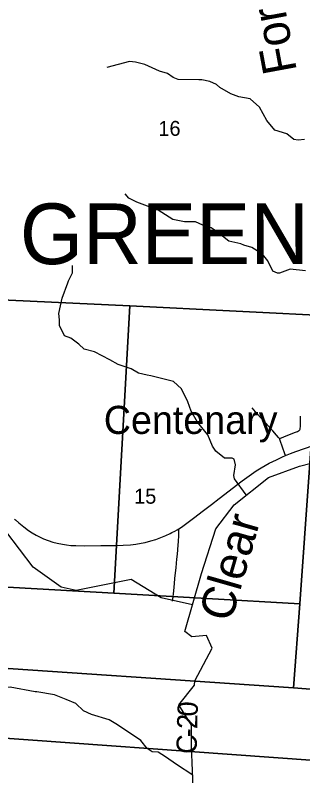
# Model space of a CAD drawing. Extents: x 0 to 34, y 0 to 22.
# Drawn here: x 24.586 to 25.392, y 17.797 to 19.934 of the extents above; entities that cross this region are included whole.
import ezdxf

# ---------------------------------------------------------------- set-up
doc = ezdxf.new("R2010")
doc.units = 0
for name, color, linetype in [('GM_X_County_Road', 7, 'Continuous'), ('GM_X_County_Road_Text', 7, 'Continuous'), ('GM_X_Minor_River', 7, 'Continuous'), ('GM_X_Minor_River_Text', 7, 'Continuous'), ('GM_X_Section', 7, 'Continuous'), ('GM_X_Section_Text', 7, 'Continuous'), ('GM_X_State_Route', 7, 'Continuous'), ('GM_X_Township_Road', 7, 'Continuous'), ('GM_X_Township_Text', 7, 'Continuous'), ('GM_X_Unincorporated_Text', 7, 'Continuous')]:
    doc.layers.add(name, color=color, linetype=linetype)

msp = doc.modelspace()

# ---------------------------------------------------------------- linework, layer by layer
at = {"layer": 'GM_X_County_Road'}
msp.add_lwpolyline([(25.0271, 18.2869), (25.0277, 18.2919), (25.0303, 18.3166), (25.0323, 18.337), (25.0337, 18.3509), (25.0354, 18.3666), (25.0368, 18.3808), (25.0382, 18.3939), (25.0393, 18.4054), (25.0405, 18.419), (25.0417, 18.4316), (25.0428, 18.4456), (25.0434, 18.4539), (25.0442, 18.4732), (25.0443, 18.4852), (25.0443, 18.4908)], dxfattribs=at)
at = {"layer": 'GM_X_Minor_River'}
for points in [[(25.3973, 19.5841), (25.3794, 19.583), (25.3669, 19.5845), (25.3472, 19.6004), (25.3142, 19.611), (25.2911, 19.6376), (25.2711, 19.6756), (25.2445, 19.6988), (25.2131, 19.7041), (25.1907, 19.7124), (25.1596, 19.7306), (25.1505, 19.739), (25.1312, 19.7477), (25.1092, 19.7518), (25.1009, 19.7518), (25.0425, 19.7529), (25.0289, 19.7586), (25.0129, 19.7704), (24.9906, 19.7768), (24.9489, 19.7954), (24.9231, 19.8022), (24.906, 19.8037), (24.8427, 19.7865)], [(25.4002, 19.2158), (25.3566, 19.2203), (25.327, 19.2089), (25.3209, 19.2085), (25.3084, 19.2145), (25.294, 19.2434), (25.2796, 19.262), (25.2497, 19.2806), (25.2273, 19.2874), (25.2182, 19.2909), (25.1849, 19.2992), (25.1493, 19.3269), (25.1348, 19.336), (25.122, 19.3394), (25.0909, 19.3534), (25.0602, 19.3534), (25.028, 19.3598), (24.9866, 19.386), (24.9264, 19.4084), (24.9044, 19.4194), (24.8942, 19.4323)], [(25.2332, 18.5859), (25.2006, 18.6309), (25.199, 18.6404), (25.2036, 18.67), (25.1994, 18.6864), (25.1945, 18.689), (25.1722, 18.689), (25.1483, 18.7091), (25.1392, 18.7232), (25.1263, 18.7551), (25.0971, 18.7901), (25.0789, 18.8216), (25.0702, 18.8478), (25.0517, 18.8843), (25.0293, 18.9044), (24.966, 18.9203), (24.9558, 18.9226), (24.9311, 18.9283), (24.9107, 18.94), (24.8743, 18.9525), (24.8512, 18.965), (24.808, 18.9882), (24.7792, 18.995), (24.7644, 19.0098), (24.742, 19.0265), (24.7242, 19.0329), (24.7102, 19.0618), (24.7102, 19.0782), (24.7079, 19.0953), (24.7174, 19.1386), (24.7334, 19.182), (24.7353, 19.1877), (24.7459, 19.2101), (24.7459, 19.2307)], [(25.0861, 17.7413), (25.0798, 17.8798), (25.0798, 17.9386), (25.0441, 17.9963), (25.0881, 18.0514), (25.0891, 18.0639), (25.1376, 18.1555), (25.1224, 18.191), (25.081, 18.1868), (25.0611, 18.2022), (25.1079, 18.3651), (25.1484, 18.4907), (25.1999, 18.558), (25.2957, 18.6351), (25.3826, 18.667), (25.4443, 18.6827)], [(25.0825, 18.2766), (24.9949, 18.2969), (24.9111, 18.3481), (24.7563, 18.3171), (24.7148, 18.3263), (24.6358, 18.3825), (24.5593, 18.4839)], [(25.0835, 17.7983), (25.0376, 17.8285), (25.0069, 17.8501), (24.9869, 17.8627), (24.9698, 17.8645), (24.9562, 17.8737), (24.9376, 17.8961), (24.8728, 17.9401), (24.8489, 17.9538), (24.7996, 17.9689), (24.7769, 17.9795), (24.7561, 18), (24.7284, 18.0107), (24.6954, 18.0239), (24.6461, 18.0322), (24.6416, 18.033), (24.5711, 18.0455), (24.54, 18.0409), (24.5021, 18.0446), (24.4869, 18.0457), (24.4562, 18.0396), (24.424, 18.0415), (24.3853, 18.0434), (24.3577, 18.0384)]]:
    msp.add_lwpolyline(points, dxfattribs=at)
at = {"layer": 'GM_X_Section'}
for points in [[(24.5388, 20.1708), (25.5703, 20.1097), (25.5433, 19.6923), (25.5164, 19.2759), (25.5041, 19.0909), (25.5038, 19.0874), (24.9075, 19.1174), (24.4668, 19.1382), (24.4804, 19.3317), (24.5096, 19.7459)], [(24.4668, 19.1382), (24.9075, 19.1174), (24.8626, 18.3102), (24.4145, 18.3347), (24.4515, 18.9043)], [(24.9075, 19.1174), (25.5038, 19.0874), (25.4882, 18.8408), (25.4244, 18.8461), (25.3836, 18.2803), (24.8626, 18.3102)], [(25.4882, 18.8408), (25.4369, 18.0387), (25.3665, 18.0434), (25.3836, 18.2803), (25.4244, 18.8461)], [(24.8626, 18.3102), (25.3836, 18.2803), (25.3665, 18.0434), (24.3998, 18.1092), (24.4145, 18.3347)], [(24.3998, 18.1092), (25.3665, 18.0434), (25.4369, 18.0387), (25.4267, 17.8394), (24.3871, 17.9146)], [(25.4267, 17.8394), (25.3999, 17.4262), (24.3605, 17.505), (24.3871, 17.9146)]]:
    msp.add_lwpolyline(points, close=True, dxfattribs=at)
at = {"layer": 'GM_X_State_Route'}
for points in [[(25.0253, 18.4802), (25.0333, 18.4843), (25.0403, 18.4881), (25.0443, 18.4908), (25.0518, 18.4956), (25.0631, 18.5035), (25.0855, 18.5202), (25.114, 18.5422), (25.1358, 18.5587), (25.1579, 18.5759), (25.2226, 18.6252), (25.2416, 18.6392), (25.2614, 18.6531), (25.2757, 18.6619), (25.2983, 18.6748), (25.3182, 18.6849), (25.3356, 18.6931), (25.3437, 18.6965), (25.3579, 18.7026), (25.3724, 18.7081), (25.4212, 18.7244)], [(24.5839, 18.5175), (24.586, 18.5156), (24.5958, 18.5071), (24.6099, 18.4958), (24.623, 18.4862), (24.6329, 18.4797), (24.6446, 18.4727), (24.654, 18.4678), (24.6648, 18.4629), (24.6782, 18.4577), (24.6907, 18.4536), (24.7033, 18.4503), (24.718, 18.4473), (24.7291, 18.4456), (24.7415, 18.4442), (24.7558, 18.4435), (24.7788, 18.4433), (24.826, 18.444), (24.8471, 18.444), (24.8713, 18.4441), (24.8888, 18.4444), (24.9093, 18.4459), (24.9235, 18.4475), (24.9389, 18.4499), (24.9505, 18.4524), (24.9661, 18.4565), (24.9798, 18.4606), (24.9938, 18.4658), (25.0082, 18.4718), (25.0199, 18.4775), (25.0253, 18.4802)]]:
    msp.add_lwpolyline(points, dxfattribs=at)
at = {"layer": 'GM_X_Township_Road'}
for points in [[(25.3437, 18.6965), (25.342, 18.7014), (25.3287, 18.7392), (25.3272, 18.744), (25.3244, 18.7471), (25.3188, 18.7536), (25.3082, 18.7659), (25.2868, 18.7891), (25.2644, 18.814), (25.2504, 18.8307)], [(25.3272, 18.744), (25.3322, 18.7464), (25.3395, 18.7495), (25.3455, 18.7519), (25.3722, 18.7618), (25.3778, 18.7641), (25.3804, 18.7655), (25.3822, 18.7668), (25.3836, 18.7686), (25.3845, 18.7706), (25.3851, 18.7735), (25.3854, 18.7773), (25.3856, 18.7809), (25.3858, 18.7942), (25.3856, 18.8074)]]:
    msp.add_lwpolyline(points, dxfattribs=at)

# ---------------------------------------------------------------- texts
at = {"layer": 'GM_X_County_Road_Text'}
for s, rotation, p in [('0', 87.418, (25.0968, 17.9623)), ('2', 88.5636, (25.096, 17.9276)), ('C', 88.8251, (25.0945, 17.8577)), ('-', 88.7743, (25.0955, 17.9044))]:
    msp.add_text(s, height=0.0568, rotation=rotation, dxfattribs=at).set_placement(p)
at = {"layer": 'GM_X_Minor_River_Text'}
for s, height, rotation, p in [('Fork', 0.09468, 100.5169, (25.376, 19.7774)), ('Clear', 0.09469, 73.9989, (25.1908, 18.2252))]:
    msp.add_text(s, height=height, rotation=rotation, dxfattribs=at).set_placement(p)
at = {"layer": 'GM_X_Section_Text'}
for s, p in [('16', (24.9871, 19.5948)), ('15', (24.9191, 18.5612))]:
    msp.add_text(s, height=0.04186, rotation=0, dxfattribs=at).set_placement(p)
at = {"layer": 'GM_X_Township_Text'}
msp.add_text('GREEN', height=0.17045, rotation=0, dxfattribs=at).set_placement((24.5988, 19.2343))
at = {"layer": 'GM_X_Unincorporated_Text'}
msp.add_text('Centenary', height=0.07898, rotation=0, dxfattribs=at).set_placement((24.8341, 18.7572))

doc.saveas('drawing.dxf')
